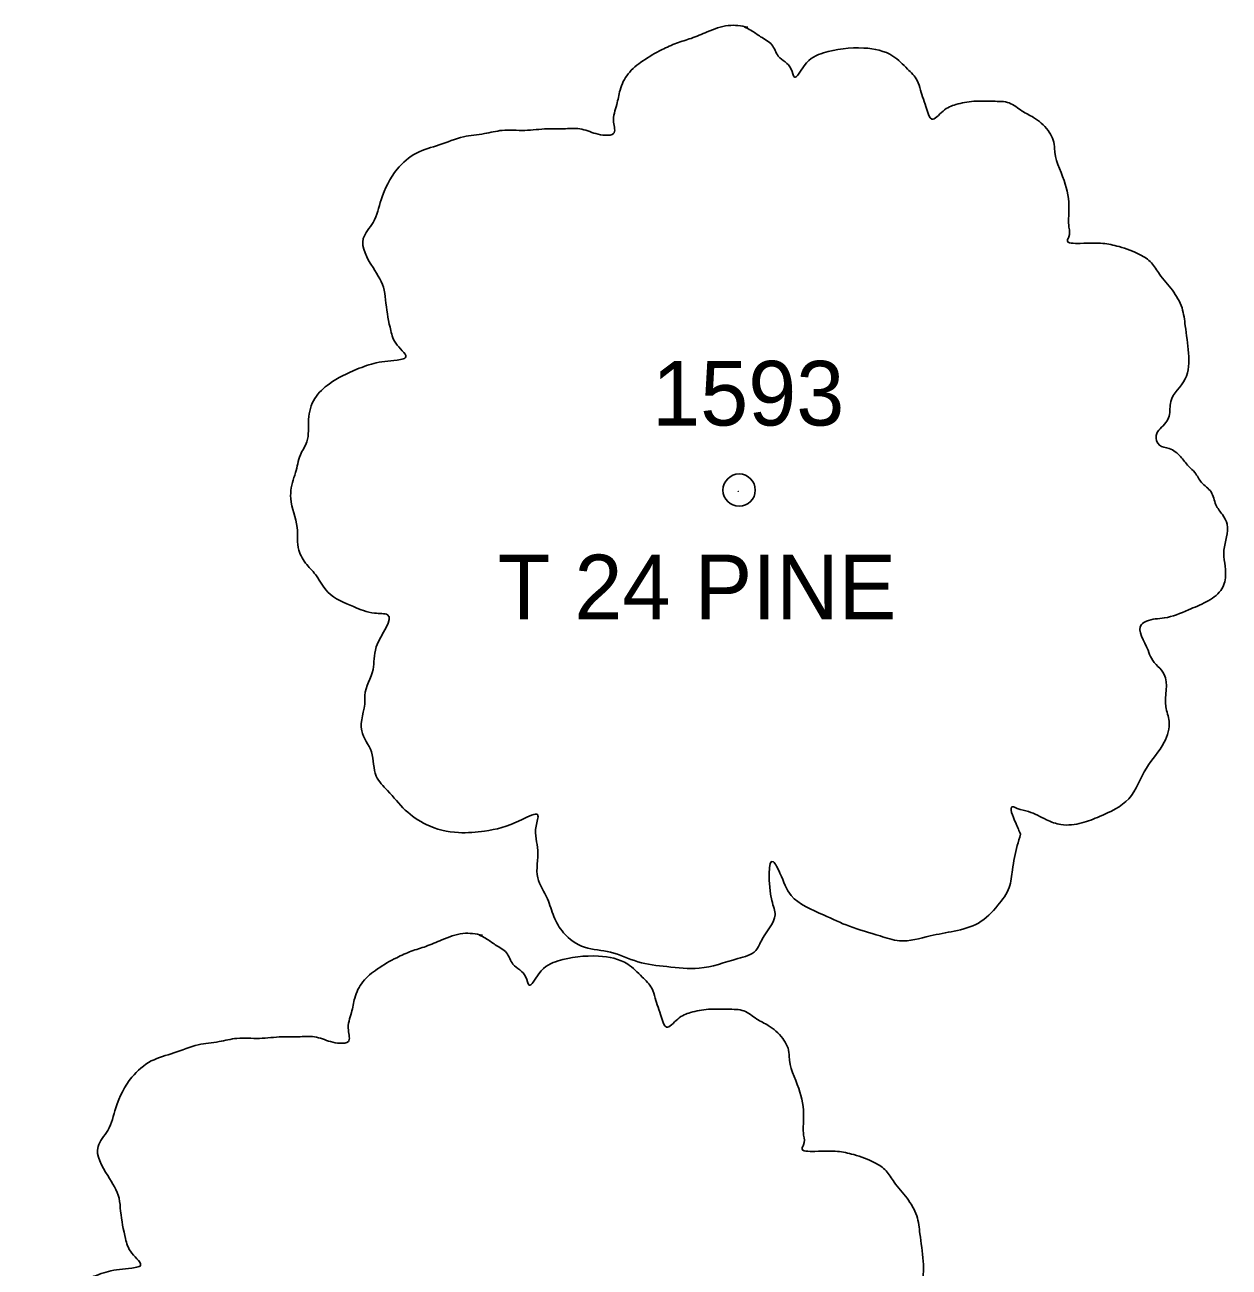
# Model space of a CAD drawing. Extents: x 1965304 to 1970247, y 1117014 to 1118201.
# Drawn here: x 1966638.05 to 1966656.68, y 1117457.62 to 1117476.85 of the extents above; entities that cross this region are included whole.
import ezdxf

# ---------------------------------------------------------------- set-up
doc = ezdxf.new("R2010")
doc.units = 0
doc.layers.add('RD_EX_VEG', color=7, linetype='Continuous')
doc.layers.add('RD_EX_VEG_txCode', color=7, linetype='Continuous')

msp = doc.modelspace()

# ---------------------------------------------------------------- linework, layer by layer
at = {"layer": 'RD_EX_VEG'}
for centre, radius in [((1966649.1, 1117469.652), 0.25), ((1966649.1, 1117469.652), 0.25), ((1966649.087, 1117469.633), 0.0001), ((1966649.087, 1117469.633), 0.0001)]:
    msp.add_circle(centre, radius, dxfattribs=at)
for points in [[(1966649.232, 1117476.819), (1966648.932, 1117476.844), (1966648.607, 1117476.744), (1966648.357, 1117476.645), (1966648.132, 1117476.57), (1966647.907, 1117476.47), (1966647.607, 1117476.295), (1966647.382, 1117476.095), (1966647.257, 1117475.845), (1966647.207, 1117475.62), (1966647.158, 1117475.345), (1966647.158, 1117475.17), (1966647.033, 1117475.145), (1966646.883, 1117475.17), (1966646.633, 1117475.245), (1966646.383, 1117475.245), (1966646.133, 1117475.245), (1966645.783, 1117475.22), (1966645.433, 1117475.22), (1966645.158, 1117475.17), (1966644.834, 1117475.12), (1966644.459, 1117474.995), (1966644.109, 1117474.87), (1966643.809, 1117474.62), (1966643.559, 1117474.146), (1966643.434, 1117473.796), (1966643.284, 1117473.546), (1966643.434, 1117473.096), (1966643.609, 1117472.746), (1966643.634, 1117472.546), (1966643.709, 1117472.122), (1966643.809, 1117471.897), (1966643.934, 1117471.697), (1966643.859, 1117471.672), (1966643.484, 1117471.622), (1966643.184, 1117471.522), (1966642.759, 1117471.297), (1966642.535, 1117471.072), (1966642.435, 1117470.747), (1966642.41, 1117470.397), (1966642.31, 1117470.197), (1966642.235, 1117469.922), (1966642.21, 1117469.847), (1966642.16, 1117469.523), (1966642.26, 1117469.073), (1966642.285, 1117468.723), (1966642.41, 1117468.498), (1966642.56, 1117468.323), (1966642.734, 1117468.073), (1966643.134, 1117467.848), (1966643.459, 1117467.748), (1966643.659, 1117467.723), (1966643.484, 1117467.224), (1966643.434, 1117466.874), (1966643.309, 1117466.474), (1966643.309, 1117466.399), (1966643.259, 1117465.924), (1966643.409, 1117465.599), (1966643.484, 1117465.225), (1966643.659, 1117465), (1966643.934, 1117464.7), (1966644.259, 1117464.475), (1966644.759, 1117464.35), (1966645.158, 1117464.375), (1966645.733, 1117464.55), (1966645.983, 1117464.625), (1966645.958, 1117464.45), (1966645.983, 1117464.075), (1966645.983, 1117463.65), (1966646.133, 1117463.325), (1966646.233, 1117463.05), (1966646.383, 1117462.801), (1966646.708, 1117462.576), (1966647.108, 1117462.501), (1966647.532, 1117462.351), (1966647.982, 1117462.276), (1966648.482, 1117462.251), (1966649.082, 1117462.401), (1966649.357, 1117462.526), (1966649.457, 1117462.701), (1966649.656, 1117463.075), (1966649.606, 1117463.3), (1966649.631, 1117463.9), (1966649.731, 1117463.725), (1966649.906, 1117463.375), (1966650.406, 1117463.075), (1966650.806, 1117462.901), (1966651.281, 1117462.751), (1966651.581, 1117462.676), (1966652.055, 1117462.751), (1966652.43, 1117462.826), (1966652.805, 1117462.951), (1966653.105, 1117463.225), (1966653.28, 1117463.5), (1966653.33, 1117463.775), (1966653.405, 1117464.15), (1966653.455, 1117464.325)], [(1966649.232, 1117476.819), (1966648.932, 1117476.844), (1966648.607, 1117476.744), (1966648.357, 1117476.645), (1966648.132, 1117476.57), (1966647.907, 1117476.47), (1966647.607, 1117476.295), (1966647.382, 1117476.095), (1966647.257, 1117475.845), (1966647.207, 1117475.62), (1966647.158, 1117475.345), (1966647.158, 1117475.17), (1966647.033, 1117475.145), (1966646.883, 1117475.17), (1966646.633, 1117475.245), (1966646.383, 1117475.245), (1966646.133, 1117475.245), (1966645.783, 1117475.22), (1966645.433, 1117475.22), (1966645.158, 1117475.17), (1966644.834, 1117475.12), (1966644.459, 1117474.995), (1966644.109, 1117474.87), (1966643.809, 1117474.62), (1966643.559, 1117474.146), (1966643.434, 1117473.796), (1966643.284, 1117473.546), (1966643.434, 1117473.096), (1966643.609, 1117472.746), (1966643.634, 1117472.546), (1966643.709, 1117472.122), (1966643.809, 1117471.897), (1966643.934, 1117471.697), (1966643.859, 1117471.672), (1966643.484, 1117471.622), (1966643.184, 1117471.522), (1966642.759, 1117471.297), (1966642.535, 1117471.072), (1966642.435, 1117470.747), (1966642.41, 1117470.397), (1966642.31, 1117470.197), (1966642.235, 1117469.922), (1966642.21, 1117469.847), (1966642.16, 1117469.523), (1966642.26, 1117469.073), (1966642.285, 1117468.723), (1966642.41, 1117468.498), (1966642.56, 1117468.323), (1966642.734, 1117468.073), (1966643.134, 1117467.848), (1966643.459, 1117467.748), (1966643.659, 1117467.723), (1966643.484, 1117467.224), (1966643.434, 1117466.874), (1966643.309, 1117466.474), (1966643.309, 1117466.399), (1966643.259, 1117465.924), (1966643.409, 1117465.599), (1966643.484, 1117465.225), (1966643.659, 1117465), (1966643.934, 1117464.7), (1966644.259, 1117464.475), (1966644.759, 1117464.35), (1966645.158, 1117464.375), (1966645.733, 1117464.55), (1966645.983, 1117464.625), (1966645.958, 1117464.45), (1966645.983, 1117464.075), (1966645.983, 1117463.65), (1966646.133, 1117463.325), (1966646.233, 1117463.05), (1966646.383, 1117462.801), (1966646.708, 1117462.576), (1966647.108, 1117462.501), (1966647.532, 1117462.351), (1966647.982, 1117462.276), (1966648.482, 1117462.251), (1966649.082, 1117462.401), (1966649.357, 1117462.526), (1966649.457, 1117462.701), (1966649.656, 1117463.075), (1966649.606, 1117463.3), (1966649.631, 1117463.9), (1966649.731, 1117463.725), (1966649.906, 1117463.375), (1966650.406, 1117463.075), (1966650.806, 1117462.901), (1966651.281, 1117462.751), (1966651.581, 1117462.676), (1966652.055, 1117462.751), (1966652.43, 1117462.826), (1966652.805, 1117462.951), (1966653.105, 1117463.225), (1966653.28, 1117463.5), (1966653.33, 1117463.775), (1966653.405, 1117464.15), (1966653.455, 1117464.325)], [(1966653.455, 1117464.325), (1966653.38, 1117464.5), (1966653.33, 1117464.75), (1966653.405, 1117464.725), (1966653.58, 1117464.675), (1966653.855, 1117464.55), (1966654.08, 1117464.475), (1966654.404, 1117464.5), (1966654.679, 1117464.6), (1966655.129, 1117464.875), (1966655.404, 1117465.349), (1966655.679, 1117465.749), (1966655.754, 1117466.074), (1966655.704, 1117466.299), (1966655.679, 1117466.799), (1966655.479, 1117467.049), (1966655.429, 1117467.174), (1966655.329, 1117467.573), (1966655.404, 1117467.623), (1966655.679, 1117467.673), (1966656.054, 1117467.798), (1966656.329, 1117467.923), (1966656.553, 1117468.098), (1966656.628, 1117468.323), (1966656.603, 1117468.723), (1966656.653, 1117469.123), (1966656.578, 1117469.273), (1966656.478, 1117469.423), (1966656.403, 1117469.623), (1966656.254, 1117469.772), (1966656.154, 1117469.922), (1966656.054, 1117470.022), (1966655.929, 1117470.172), (1966655.754, 1117470.297), (1966655.604, 1117470.347), (1966655.554, 1117470.497), (1966655.704, 1117470.697), (1966655.754, 1117470.797), (1966655.779, 1117471.022), (1966656.004, 1117471.372), (1966656.054, 1117471.772), (1966656.004, 1117472.196), (1966655.954, 1117472.471), (1966655.804, 1117472.746), (1966655.604, 1117472.996), (1966655.479, 1117473.171), (1966655.304, 1117473.296), (1966654.979, 1117473.421), (1966654.729, 1117473.471), (1966654.379, 1117473.471), (1966654.179, 1117473.521), (1966654.204, 1117473.571), (1966654.204, 1117473.721), (1966654.204, 1117473.996), (1966654.129, 1117474.445), (1966653.98, 1117474.945), (1966653.98, 1117474.97), (1966653.88, 1117475.22), (1966653.655, 1117475.42), (1966653.48, 1117475.52), (1966653.28, 1117475.645), (1966653.03, 1117475.67), (1966652.73, 1117475.67), (1966652.455, 1117475.62), (1966652.255, 1117475.52), (1966652.08, 1117475.395), (1966652.005, 1117475.545), (1966651.905, 1117475.845), (1966651.855, 1117475.995), (1966651.706, 1117476.17), (1966651.481, 1117476.37), (1966651.031, 1117476.495), (1966650.406, 1117476.42), (1966650.106, 1117476.22), (1966649.956, 1117476.045), (1966649.906, 1117476.17), (1966649.706, 1117476.37), (1966649.606, 1117476.545), (1966649.432, 1117476.67), (1966649.282, 1117476.769), (1966649.182, 1117476.819)], [(1966653.455, 1117464.325), (1966653.38, 1117464.5), (1966653.33, 1117464.75), (1966653.405, 1117464.725), (1966653.58, 1117464.675), (1966653.855, 1117464.55), (1966654.08, 1117464.475), (1966654.404, 1117464.5), (1966654.679, 1117464.6), (1966655.129, 1117464.875), (1966655.404, 1117465.349), (1966655.679, 1117465.749), (1966655.754, 1117466.074), (1966655.704, 1117466.299), (1966655.679, 1117466.799), (1966655.479, 1117467.049), (1966655.429, 1117467.174), (1966655.329, 1117467.573), (1966655.404, 1117467.623), (1966655.679, 1117467.673), (1966656.054, 1117467.798), (1966656.329, 1117467.923), (1966656.553, 1117468.098), (1966656.628, 1117468.323), (1966656.603, 1117468.723), (1966656.653, 1117469.123), (1966656.578, 1117469.273), (1966656.478, 1117469.423), (1966656.403, 1117469.623), (1966656.254, 1117469.772), (1966656.154, 1117469.922), (1966656.054, 1117470.022), (1966655.929, 1117470.172), (1966655.754, 1117470.297), (1966655.604, 1117470.347), (1966655.554, 1117470.497), (1966655.704, 1117470.697), (1966655.754, 1117470.797), (1966655.779, 1117471.022), (1966656.004, 1117471.372), (1966656.054, 1117471.772), (1966656.004, 1117472.196), (1966655.954, 1117472.471), (1966655.804, 1117472.746), (1966655.604, 1117472.996), (1966655.479, 1117473.171), (1966655.304, 1117473.296), (1966654.979, 1117473.421), (1966654.729, 1117473.471), (1966654.379, 1117473.471), (1966654.179, 1117473.521), (1966654.204, 1117473.571), (1966654.204, 1117473.721), (1966654.204, 1117473.996), (1966654.129, 1117474.445), (1966653.98, 1117474.945), (1966653.98, 1117474.97), (1966653.88, 1117475.22), (1966653.655, 1117475.42), (1966653.48, 1117475.52), (1966653.28, 1117475.645), (1966653.03, 1117475.67), (1966652.73, 1117475.67), (1966652.455, 1117475.62), (1966652.255, 1117475.52), (1966652.08, 1117475.395), (1966652.005, 1117475.545), (1966651.905, 1117475.845), (1966651.855, 1117475.995), (1966651.706, 1117476.17), (1966651.481, 1117476.37), (1966651.031, 1117476.495), (1966650.406, 1117476.42), (1966650.106, 1117476.22), (1966649.956, 1117476.045), (1966649.906, 1117476.17), (1966649.706, 1117476.37), (1966649.606, 1117476.545), (1966649.432, 1117476.67), (1966649.282, 1117476.769), (1966649.182, 1117476.819)], [(1966645.126, 1117462.764), (1966644.826, 1117462.789), (1966644.501, 1117462.689), (1966644.251, 1117462.589), (1966644.026, 1117462.514), (1966643.801, 1117462.414), (1966643.501, 1117462.24), (1966643.276, 1117462.04), (1966643.151, 1117461.79), (1966643.101, 1117461.565), (1966643.052, 1117461.29), (1966643.052, 1117461.115), (1966642.927, 1117461.09), (1966642.777, 1117461.115), (1966642.527, 1117461.19), (1966642.277, 1117461.19), (1966642.027, 1117461.19), (1966641.677, 1117461.165), (1966641.327, 1117461.165), (1966641.052, 1117461.115), (1966640.728, 1117461.065), (1966640.353, 1117460.94), (1966640.003, 1117460.815), (1966639.703, 1117460.565), (1966639.453, 1117460.09), (1966639.328, 1117459.741), (1966639.178, 1117459.491), (1966639.328, 1117459.041), (1966639.503, 1117458.691), (1966639.528, 1117458.491), (1966639.603, 1117458.066), (1966639.703, 1117457.841), (1966639.828, 1117457.641), (1966639.753, 1117457.617), (1966639.378, 1117457.567), (1966639.078, 1117457.467), (1966638.653, 1117457.242), (1966638.429, 1117457.017), (1966638.329, 1117456.692), (1966638.304, 1117456.342), (1966638.204, 1117456.142), (1966638.129, 1117455.867), (1966638.104, 1117455.792), (1966638.054, 1117455.467), (1966638.154, 1117455.018), (1966638.179, 1117454.668), (1966638.304, 1117454.443), (1966638.454, 1117454.268), (1966638.628, 1117454.018), (1966639.028, 1117453.793), (1966639.353, 1117453.693), (1966639.553, 1117453.668), (1966639.378, 1117453.168), (1966639.328, 1117452.819), (1966639.203, 1117452.419), (1966639.203, 1117452.344), (1966639.153, 1117451.869), (1966639.303, 1117451.544), (1966639.378, 1117451.169), (1966639.553, 1117450.944), (1966639.828, 1117450.645), (1966640.153, 1117450.42), (1966640.653, 1117450.295), (1966641.052, 1117450.32), (1966641.627, 1117450.495), (1966641.877, 1117450.57), (1966641.852, 1117450.395), (1966641.877, 1117450.02), (1966641.877, 1117449.595), (1966642.027, 1117449.27), (1966642.127, 1117448.995), (1966642.277, 1117448.745), (1966642.602, 1117448.521), (1966643.002, 1117448.446), (1966643.426, 1117448.296), (1966643.876, 1117448.221), (1966644.376, 1117448.196), (1966644.976, 1117448.346), (1966645.251, 1117448.471), (1966645.351, 1117448.645), (1966645.55, 1117449.02), (1966645.5, 1117449.245), (1966645.525, 1117449.845), (1966645.625, 1117449.67), (1966645.8, 1117449.32), (1966646.3, 1117449.02), (1966646.7, 1117448.845), (1966647.175, 1117448.695), (1966647.475, 1117448.62), (1966647.949, 1117448.695), (1966648.324, 1117448.77), (1966648.699, 1117448.895), (1966648.999, 1117449.17), (1966649.174, 1117449.445), (1966649.224, 1117449.72), (1966649.299, 1117450.095), (1966649.349, 1117450.27)], [(1966645.126, 1117462.764), (1966644.826, 1117462.789), (1966644.501, 1117462.689), (1966644.251, 1117462.589), (1966644.026, 1117462.514), (1966643.801, 1117462.414), (1966643.501, 1117462.24), (1966643.276, 1117462.04), (1966643.151, 1117461.79), (1966643.101, 1117461.565), (1966643.052, 1117461.29), (1966643.052, 1117461.115), (1966642.927, 1117461.09), (1966642.777, 1117461.115), (1966642.527, 1117461.19), (1966642.277, 1117461.19), (1966642.027, 1117461.19), (1966641.677, 1117461.165), (1966641.327, 1117461.165), (1966641.052, 1117461.115), (1966640.728, 1117461.065), (1966640.353, 1117460.94), (1966640.003, 1117460.815), (1966639.703, 1117460.565), (1966639.453, 1117460.09), (1966639.328, 1117459.741), (1966639.178, 1117459.491), (1966639.328, 1117459.041), (1966639.503, 1117458.691), (1966639.528, 1117458.491), (1966639.603, 1117458.066), (1966639.703, 1117457.841), (1966639.828, 1117457.641), (1966639.753, 1117457.617), (1966639.378, 1117457.567), (1966639.078, 1117457.467), (1966638.653, 1117457.242), (1966638.429, 1117457.017), (1966638.329, 1117456.692), (1966638.304, 1117456.342), (1966638.204, 1117456.142), (1966638.129, 1117455.867), (1966638.104, 1117455.792), (1966638.054, 1117455.467), (1966638.154, 1117455.018), (1966638.179, 1117454.668), (1966638.304, 1117454.443), (1966638.454, 1117454.268), (1966638.628, 1117454.018), (1966639.028, 1117453.793), (1966639.353, 1117453.693), (1966639.553, 1117453.668), (1966639.378, 1117453.168), (1966639.328, 1117452.819), (1966639.203, 1117452.419), (1966639.203, 1117452.344), (1966639.153, 1117451.869), (1966639.303, 1117451.544), (1966639.378, 1117451.169), (1966639.553, 1117450.944), (1966639.828, 1117450.645), (1966640.153, 1117450.42), (1966640.653, 1117450.295), (1966641.052, 1117450.32), (1966641.627, 1117450.495), (1966641.877, 1117450.57), (1966641.852, 1117450.395), (1966641.877, 1117450.02), (1966641.877, 1117449.595), (1966642.027, 1117449.27), (1966642.127, 1117448.995), (1966642.277, 1117448.745), (1966642.602, 1117448.521), (1966643.002, 1117448.446), (1966643.426, 1117448.296), (1966643.876, 1117448.221), (1966644.376, 1117448.196), (1966644.976, 1117448.346), (1966645.251, 1117448.471), (1966645.351, 1117448.645), (1966645.55, 1117449.02), (1966645.5, 1117449.245), (1966645.525, 1117449.845), (1966645.625, 1117449.67), (1966645.8, 1117449.32), (1966646.3, 1117449.02), (1966646.7, 1117448.845), (1966647.175, 1117448.695), (1966647.475, 1117448.62), (1966647.949, 1117448.695), (1966648.324, 1117448.77), (1966648.699, 1117448.895), (1966648.999, 1117449.17), (1966649.174, 1117449.445), (1966649.224, 1117449.72), (1966649.299, 1117450.095), (1966649.349, 1117450.27)], [(1966649.349, 1117450.27), (1966649.274, 1117450.445), (1966649.224, 1117450.695), (1966649.299, 1117450.67), (1966649.474, 1117450.62), (1966649.749, 1117450.495), (1966649.974, 1117450.42), (1966650.298, 1117450.445), (1966650.573, 1117450.545), (1966651.023, 1117450.82), (1966651.298, 1117451.294), (1966651.573, 1117451.694), (1966651.648, 1117452.019), (1966651.598, 1117452.244), (1966651.573, 1117452.744), (1966651.373, 1117452.994), (1966651.323, 1117453.118), (1966651.223, 1117453.518), (1966651.298, 1117453.568), (1966651.573, 1117453.618), (1966651.948, 1117453.743), (1966652.223, 1117453.868), (1966652.447, 1117454.043), (1966652.522, 1117454.268), (1966652.497, 1117454.668), (1966652.547, 1117455.068), (1966652.472, 1117455.218), (1966652.372, 1117455.367), (1966652.297, 1117455.567), (1966652.148, 1117455.717), (1966652.048, 1117455.867), (1966651.948, 1117455.967), (1966651.823, 1117456.117), (1966651.648, 1117456.242), (1966651.498, 1117456.292), (1966651.448, 1117456.442), (1966651.598, 1117456.642), (1966651.648, 1117456.742), (1966651.673, 1117456.967), (1966651.898, 1117457.317), (1966651.948, 1117457.716), (1966651.898, 1117458.141), (1966651.848, 1117458.416), (1966651.698, 1117458.691), (1966651.498, 1117458.941), (1966651.373, 1117459.116), (1966651.198, 1117459.241), (1966650.873, 1117459.366), (1966650.623, 1117459.416), (1966650.273, 1117459.416), (1966650.073, 1117459.466), (1966650.098, 1117459.516), (1966650.098, 1117459.666), (1966650.098, 1117459.941), (1966650.023, 1117460.39), (1966649.874, 1117460.89), (1966649.874, 1117460.915), (1966649.774, 1117461.165), (1966649.549, 1117461.365), (1966649.374, 1117461.465), (1966649.174, 1117461.59), (1966648.924, 1117461.615), (1966648.624, 1117461.615), (1966648.349, 1117461.565), (1966648.149, 1117461.465), (1966647.974, 1117461.34), (1966647.899, 1117461.49), (1966647.799, 1117461.79), (1966647.749, 1117461.94), (1966647.6, 1117462.115), (1966647.375, 1117462.314), (1966646.925, 1117462.439), (1966646.3, 1117462.364), (1966646, 1117462.165), (1966645.85, 1117461.99), (1966645.8, 1117462.115), (1966645.6, 1117462.314), (1966645.5, 1117462.489), (1966645.326, 1117462.614), (1966645.176, 1117462.714), (1966645.076, 1117462.764)], [(1966649.349, 1117450.27), (1966649.274, 1117450.445), (1966649.224, 1117450.695), (1966649.299, 1117450.67), (1966649.474, 1117450.62), (1966649.749, 1117450.495), (1966649.974, 1117450.42), (1966650.298, 1117450.445), (1966650.573, 1117450.545), (1966651.023, 1117450.82), (1966651.298, 1117451.294), (1966651.573, 1117451.694), (1966651.648, 1117452.019), (1966651.598, 1117452.244), (1966651.573, 1117452.744), (1966651.373, 1117452.994), (1966651.323, 1117453.118), (1966651.223, 1117453.518), (1966651.298, 1117453.568), (1966651.573, 1117453.618), (1966651.948, 1117453.743), (1966652.223, 1117453.868), (1966652.447, 1117454.043), (1966652.522, 1117454.268), (1966652.497, 1117454.668), (1966652.547, 1117455.068), (1966652.472, 1117455.218), (1966652.372, 1117455.367), (1966652.297, 1117455.567), (1966652.148, 1117455.717), (1966652.048, 1117455.867), (1966651.948, 1117455.967), (1966651.823, 1117456.117), (1966651.648, 1117456.242), (1966651.498, 1117456.292), (1966651.448, 1117456.442), (1966651.598, 1117456.642), (1966651.648, 1117456.742), (1966651.673, 1117456.967), (1966651.898, 1117457.317), (1966651.948, 1117457.716), (1966651.898, 1117458.141), (1966651.848, 1117458.416), (1966651.698, 1117458.691), (1966651.498, 1117458.941), (1966651.373, 1117459.116), (1966651.198, 1117459.241), (1966650.873, 1117459.366), (1966650.623, 1117459.416), (1966650.273, 1117459.416), (1966650.073, 1117459.466), (1966650.098, 1117459.516), (1966650.098, 1117459.666), (1966650.098, 1117459.941), (1966650.023, 1117460.39), (1966649.874, 1117460.89), (1966649.874, 1117460.915), (1966649.774, 1117461.165), (1966649.549, 1117461.365), (1966649.374, 1117461.465), (1966649.174, 1117461.59), (1966648.924, 1117461.615), (1966648.624, 1117461.615), (1966648.349, 1117461.565), (1966648.149, 1117461.465), (1966647.974, 1117461.34), (1966647.899, 1117461.49), (1966647.799, 1117461.79), (1966647.749, 1117461.94), (1966647.6, 1117462.115), (1966647.375, 1117462.314), (1966646.925, 1117462.439), (1966646.3, 1117462.364), (1966646, 1117462.165), (1966645.85, 1117461.99), (1966645.8, 1117462.115), (1966645.6, 1117462.314), (1966645.5, 1117462.489), (1966645.326, 1117462.614), (1966645.176, 1117462.714), (1966645.076, 1117462.764)]]:
    msp.add_spline(points, degree=3, dxfattribs=at)

# ---------------------------------------------------------------- texts
at = {"layer": 'RD_EX_VEG_txCode'}
for s, p in [('1593', (1966647.753, 1117470.652)), ('1593', (1966647.753, 1117470.652)), ('T 24 PINE', (1966645.363, 1117467.652)), ('T 24 PINE', (1966645.363, 1117467.652))]:
    msp.add_text(s, height=1, dxfattribs=at).set_placement(p)

doc.saveas('drawing.dxf')
